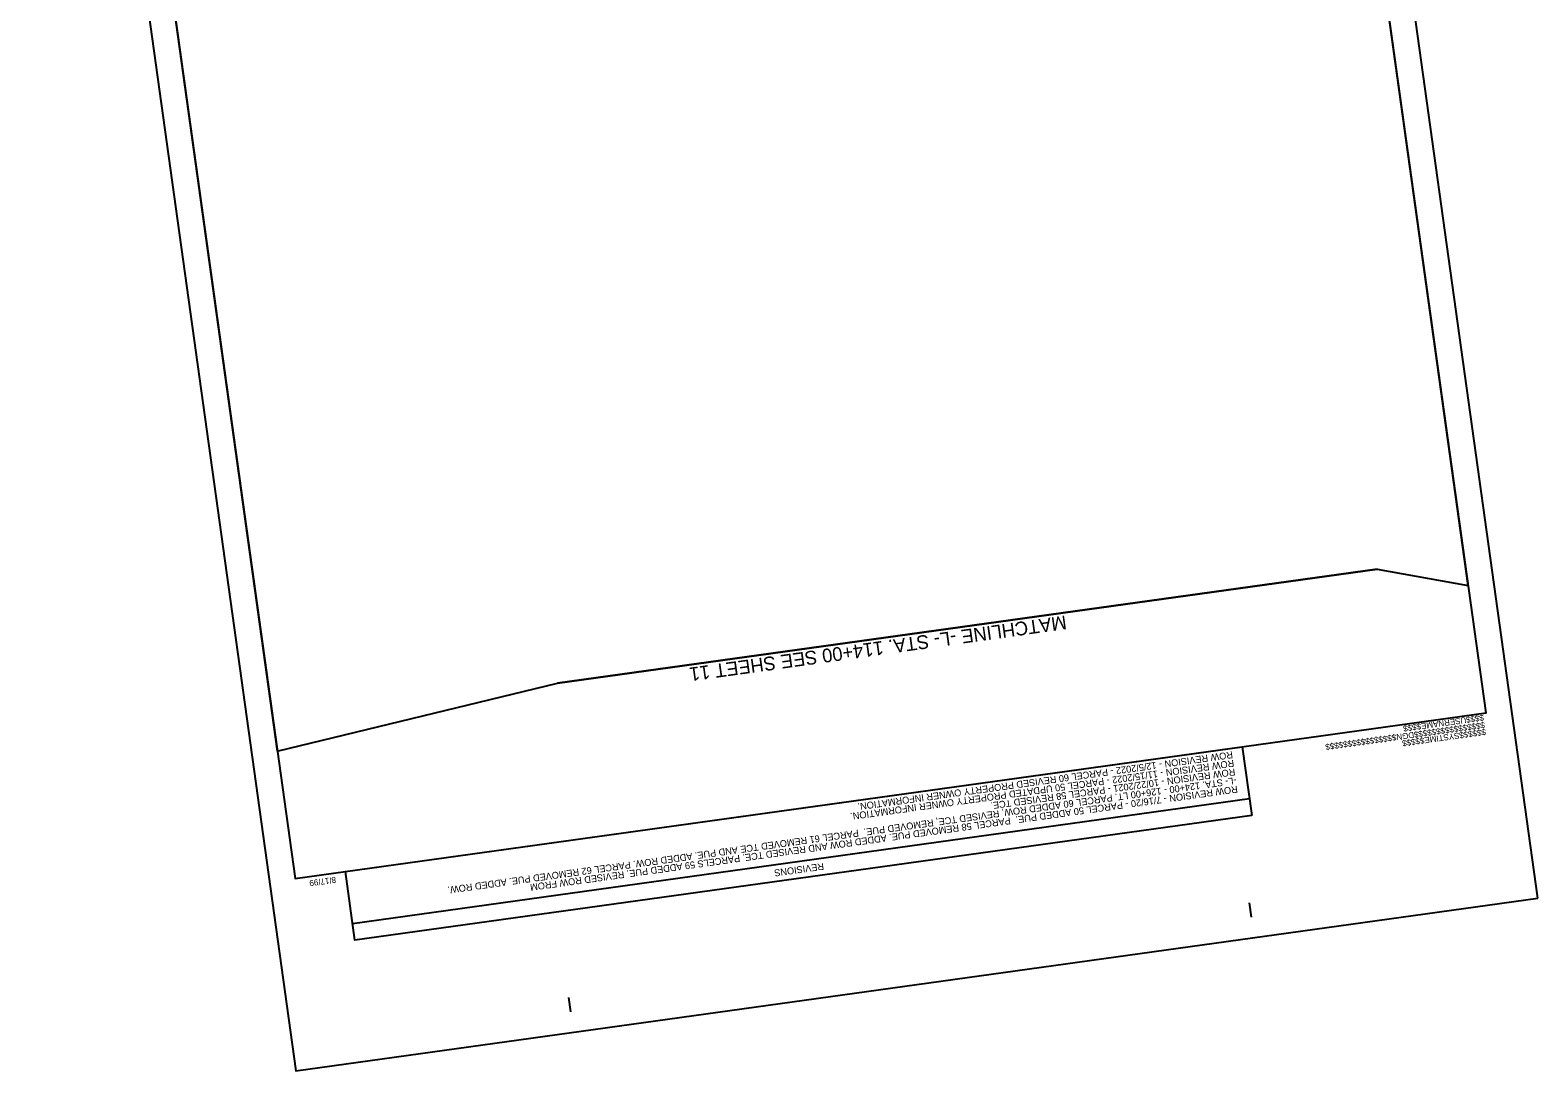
# Model space of a CAD drawing. Extents: x 477288 to 478604, y 497629 to 499448.
# Drawn here: x 477288 to 478604, y 497629 to 498538 of the extents above; entities that cross this region are included whole.
import ezdxf

# ---------------------------------------------------------------- set-up
doc = ezdxf.new("R2010")
doc.units = 0
for name, color, linetype in [('Matchline', 7, 'Continuous'), ('Matchline Text', 7, 'Continuous'), ('Sheet Block Revision CELL', 7, 'Continuous'), ('Sheet Clip Boundary CELL', 7, 'Continuous'), ('Sheet Plan CELL', 7, 'Continuous'), ('Sheet Plot Border Outside CELL', 7, 'Continuous')]:
    doc.layers.add(name, color=color, linetype=linetype)

msp = doc.modelspace()

# ---------------------------------------------------------------- linework, layer by layer
at = {"layer": 'Matchline'}
msp.add_line((478463.8, 498067.4), (477748, 497967.8), dxfattribs=at)
at = {"layer": 'Sheet Block Revision CELL'}
msp.add_line((478352.3, 497866.7), (477569.2, 497757.7), dxfattribs=at)
msp.add_lwpolyline([(478354.3, 497852.3), (477571.2, 497743.3), (477562.9, 497803.3), (478346, 497912.3)], close=True, dxfattribs=at)
at = {"layer": 'Sheet Clip Boundary CELL'}
msp.add_lwpolyline([(477503.4, 497908.5), (477748, 497967.8), (478463.8, 498067.4), (478543.4, 498053.3), (478416.5, 498965.4), (478367.6, 498958.6), (478326.8, 499251.9), (478296.4, 499247.6), (478286.2, 499322.3), (478005.3, 499240.4), (477344.9, 499047.8)], close=True, dxfattribs=at)
at = {"layer": 'Sheet Plan CELL'}
for p, q in [((478558.9, 497941.9), (478558.9, 497941.9)), ((477518.9, 497797.2), (477518.9, 497797.2)), ((478354.1, 497763.5), (478352.4, 497775.9)), ((477759.8, 497680.8), (477758.1, 497693.2))]:
    msp.add_line(p, q, dxfattribs=at)
msp.add_lwpolyline([(477312.2, 499282.9), (477518.9, 497797.2), (478558.9, 497941.9), (478352.2, 499427.6)], close=True, dxfattribs=at)
at = {"layer": 'Sheet Plot Border Outside CELL'}
msp.add_lwpolyline([(478604.2, 497780.1), (478372.1, 499447.5), (477287.6, 499296.6), (477519.6, 497629.2)], close=True, dxfattribs=at)

# ---------------------------------------------------------------- texts
at = {"layer": 'Matchline Text'}
msp.add_text('MATCHLINE -L- STA. 114+00 SEE SHEET 11', height=12, rotation=187.9227, dxfattribs=at).set_placement((478191.7, 498027.1))
at = {"layer": 'Sheet Block Revision CELL'}
for s, p in [('ROW REVISION - 11/15/2022 - PARCEL 50 UPDATED PROPERTY OWNER INFORMATION. ', (478338.5, 497900.9)), ('ROW REVISION - 12/5/2022 - PARCEL 60 REVISED PROPERTY OWNER INFORMATION. ', (478337.4, 497908.4)), ('-L- STA. 124+00 - 126+00 LT. PARCEL 60 ADDED ROW, REVISED TCE, REMOVED PUE.  PARCEL 61 REMOVED TCE AND PUE. ADDED ROW. PARCEL 62 REMOVED PUE. ADDED ROW.', (478340.6, 497885.8)), ('ROW REVISION - 10/22/2021 - PARCEL 58 REVISED TCE. ', (478339.5, 497893.4)), ('ROW REVISION - 7/16/20 - PARCEL 50 ADDED PUE.  PARCEL 58 REMOVED PUE. ADDED ROW AND REVISED TCE. PARCELS 59 ADDED PUE. REVISED ROW FROM', (478341.6, 497878.3)), ('REVISIONS', (477980.3, 497810.9))]:
    msp.add_text(s, height=6, rotation=187.9227, dxfattribs=at).set_placement(p)
at = {"layer": 'Sheet Plan CELL'}
for s, p in [('$$$$USERNAME$$$$', (478556.7, 497940.5)), ('$$$$$$$$$$$$$$$$DGN$$$$$$$$$$$$$$$$', (478557.6, 497934)), ('$$$$$$SYSTIME$$$$$', (478558.5, 497928)), ('8/17/99', (477554.3, 497798.8))]:
    msp.add_text(s, height=5.25, rotation=187.9227, dxfattribs=at).set_placement(p)

doc.saveas('drawing.dxf')
